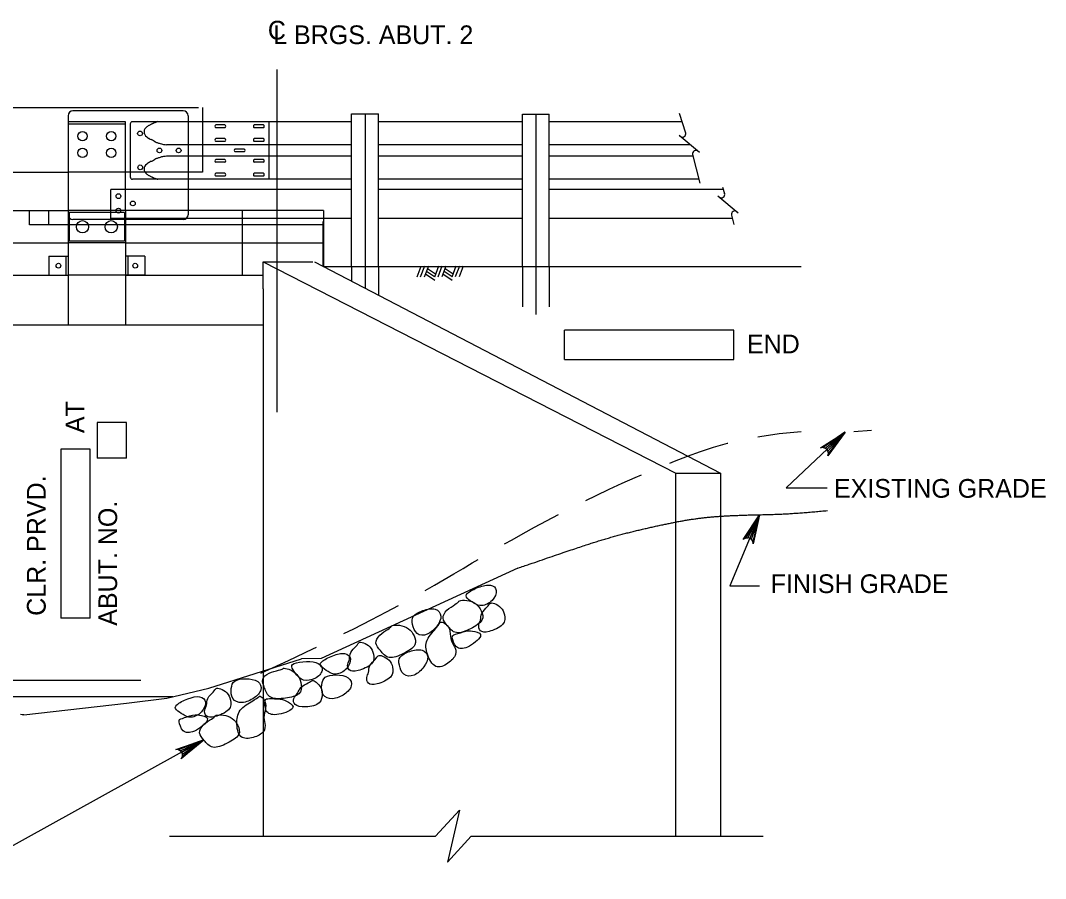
# Model space of a CAD drawing. Extents: x 638268 to 640277, y 295465 to 298435.
# Drawn here: x 638721.7 to 638886.1, y 297402.2 to 297539.8 of the extents above; entities that cross this region are included whole.
import ezdxf

# ---------------------------------------------------------------- set-up
doc = ezdxf.new("R2010")
doc.units = 0
for name, color, linetype in [('2', 7, 'Continuous'), ('3', 7, 'Continuous'), ('4', 7, 'Continuous'), ('8', 7, 'Continuous'), ('Level 25', 7, 'Continuous')]:
    doc.layers.add(name, color=color, linetype=linetype)

msp = doc.modelspace()

# ---------------------------------------------------------------- linework, layer by layer
at = {"layer": '2'}
for p, q in [((638577.23, 297525.9), (638750.23, 297525.9)), ((638750.88, 297525.9), (638750.88, 297523.59)), ((638738.57, 297523.59), (638729.33, 297523.59)), ((638729.33, 297523.59), (638729.33, 297509.34)), ((638738.57, 297523.21), (638729.33, 297523.21)), ((638738.57, 297509.34), (638738.57, 297523.59)), ((638739.3, 297523.23), (638739.3, 297514.73)), ((638750.88, 297523.6), (638739.67, 297523.6)), ((638761.47, 297523.6), (638750.88, 297523.6)), ((638750.88, 297523.59), (638750.88, 297515.51)), ((638754.49, 297523.09), (638753.02, 297523.09)), ((638754.49, 297522.63), (638753.02, 297522.63)), ((638760.67, 297523.09), (638759.19, 297523.09)), ((638760.67, 297522.63), (638759.19, 297522.63)), ((638761.54, 297523.6), (638761.54, 297514.36)), ((638774.81, 297523.6), (638761.54, 297523.6)), ((638802.21, 297523.6), (638779.14, 297523.6)), ((638827.83, 297523.6), (638806.53, 297523.6)), ((638754.49, 297520.88), (638753.02, 297520.88)), ((638754.49, 297520.41), (638753.02, 297520.41)), ((638760.67, 297520.88), (638759.19, 297520.88)), ((638760.67, 297520.41), (638759.19, 297520.41)), ((638750.88, 297519.91), (638745.14, 297519.91)), ((638774.81, 297519.91), (638750.88, 297519.91)), ((638757.59, 297519.21), (638756.11, 297519.21)), ((638757.59, 297518.75), (638756.11, 297518.75)), ((638802.21, 297519.91), (638779.14, 297519.91)), ((638829.15, 297519.91), (638806.53, 297519.91)), ((638750.88, 297518.06), (638745.14, 297518.06)), ((638774.81, 297518.06), (638750.88, 297518.06)), ((638754.49, 297517.55), (638753.02, 297517.55)), ((638754.49, 297517.09), (638753.02, 297517.09)), ((638760.67, 297517.55), (638759.19, 297517.55)), ((638760.67, 297517.09), (638759.19, 297517.09)), ((638802.21, 297518.06), (638779.14, 297518.06)), ((638829.59, 297518.06), (638806.53, 297518.06)), ((638688.94, 297515.51), (638729.33, 297515.51)), ((638738.57, 297515.51), (638729.33, 297515.51)), ((638748.58, 297515.51), (638738.57, 297515.51)), ((638750.88, 297515.51), (638748.58, 297515.51)), ((638748.58, 297514.36), (638739.67, 297514.36)), ((638774.81, 297514.36), (638748.58, 297514.36)), ((638754.49, 297515.33), (638753.02, 297515.33)), ((638754.49, 297514.87), (638753.02, 297514.87)), ((638760.67, 297515.33), (638759.19, 297515.33)), ((638760.67, 297514.87), (638759.19, 297514.87)), ((638802.21, 297514.36), (638779.14, 297514.36)), ((638830.52, 297514.36), (638806.53, 297514.36)), ((638736.22, 297508.08), (638736.22, 297512.7)), ((638748.58, 297512.7), (638736.22, 297512.7)), ((638774.81, 297512.7), (638748.58, 297512.7)), ((638802.21, 297512.7), (638779.14, 297512.7)), ((638834.45, 297512.7), (638806.53, 297512.7)), ((638688.94, 297509.34), (638729.33, 297509.34)), ((638723.16, 297507.04), (638723.16, 297509.34)), ((638726.25, 297507.04), (638726.25, 297509.34)), ((638738.57, 297509.34), (638729.33, 297509.34)), ((638729.33, 297509.34), (638729.33, 297491.02)), ((638738.41, 297509.06), (638729.52, 297509.06)), ((638729.52, 297509.06), (638729.52, 297504.45)), ((638738.41, 297509.06), (638738.41, 297504.45)), ((638770.32, 297509.34), (638738.57, 297509.34)), ((638738.57, 297509.34), (638738.57, 297491.02)), ((638748.58, 297509.34), (638748.58, 297508.68)), ((638770.3, 297508.08), (638736.21, 297508.08)), ((638774.81, 297508.08), (638770.32, 297508.08)), ((638802.21, 297508.08), (638779.14, 297508.08)), ((638835.9, 297508.08), (638806.53, 297508.08)), ((638770.3, 297507.04), (638723.15, 297507.04)), ((638688.94, 297504.15), (638729.33, 297504.15)), ((638738.57, 297504.15), (638729.33, 297504.15)), ((638738.41, 297504.45), (638729.52, 297504.45)), ((638726.24, 297502.05), (638729.33, 297502.05)), ((638726.24, 297502.05), (638726.24, 297498.96)), ((638728.97, 297502.05), (638728.97, 297498.96)), ((638729.33, 297502.05), (638729.33, 297498.96)), ((638741.66, 297502.05), (638738.57, 297502.05)), ((638738.57, 297502.05), (638738.57, 297498.96)), ((638738.93, 297502.05), (638738.93, 297498.96)), ((638741.66, 297502.05), (638741.66, 297498.96)), ((638726.24, 297498.96), (638729.33, 297498.96)), ((638738.57, 297498.96), (638729.33, 297498.96)), ((638741.66, 297498.96), (638738.57, 297498.96))]:
    msp.add_line(p, q, dxfattribs=at)
for centre, radius in [((638731.65, 297521.28), 0.748), ((638736.26, 297521.28), 0.748), ((638740.88, 297521.72), 0.385), ((638731.65, 297518.59), 0.748), ((638736.26, 297518.59), 0.748), ((638743.99, 297518.99), 0.385), ((638747.07, 297518.99), 0.385), ((638740.91, 297516.27), 0.385), ((638737.41, 297511.65), 0.385), ((638739.72, 297510.49), 0.385), ((638737.41, 297509.34), 0.385), ((638731.65, 297506.75), 0.978), ((638736.26, 297506.75), 0.978), ((638727.79, 297500.5), 0.385), ((638740.11, 297500.5), 0.385)]:
    msp.add_circle(centre, radius, dxfattribs=at)
for centre, radius, start, end in [((638739.67, 297523.23), 0.369, 90, 180), ((638742.44, 297521.97), 0.916, 120.3532, 238.6149), ((638744.76, 297519.33), 4.42, 125.3229, 129.0151), ((638742.76, 297522.15), 0.955, 117.3798, 125.3229), ((638756.95, 297494.76), 31.8, 116.5749, 117.3798), ((638743.8, 297521.04), 2.42, 113.6547, 116.5749), ((638745.21, 297517.82), 5.93, 112.3149, 113.6547), ((638767.53, 297463.43), 64.73, 111.9093, 112.3149), ((638744.08, 297521.73), 1.88, 108.4934, 111.9093), ((638746.71, 297513.88), 10.17, 107.0234, 108.4934), ((638753.16, 297522.86), 0.269, 120.8559, 239.1441), ((638754.36, 297522.86), 0.269, 300.8559, 59.1441), ((638759.33, 297522.86), 0.269, 120.8559, 239.1441), ((638760.53, 297522.86), 0.269, 300.8559, 59.1441), ((638745.19, 297524.93), 4.94, 229.2007, 233.1182), ((638742.88, 297521.85), 1.09, 233.1182, 241.475), ((638929.96, 297866.04), 392.83, 241.475, 241.5275), ((638682.44, 297409.64), 126.36, 61.435, 61.5275), ((638687.83, 297419.55), 115.08, 61.2499, 61.435), ((638753.5, 297539.25), 21.45, 241.2499, 241.6785), ((638743.63, 297520.93), 0.644, 241.6785, 249.7671), ((638753.16, 297520.65), 0.269, 120.8559, 239.1441), ((638754.36, 297520.65), 0.269, 300.8559, 59.1441), ((638759.33, 297520.65), 0.269, 120.8559, 239.1441), ((638760.53, 297520.65), 0.269, 300.8559, 59.1441), ((638749.69, 297537.38), 18.18, 249.7671, 251.2889), ((638744.87, 297523.15), 3.14, 251.2889, 252.6389), ((638771.37, 297607.92), 91.96, 252.6389, 252.8885), ((638744.95, 297522.09), 2.16, 252.8885, 261.633), ((638745.37, 297524.93), 5.03, 261.633, 267.3571), ((638756.25, 297518.98), 0.269, 120.8559, 239.1441), ((638757.45, 297518.98), 0.269, 300.8559, 59.1441), ((638742.88, 297516.12), 1.09, 118.525, 126.8818), ((638929.96, 297171.93), 392.83, 118.4725, 118.525), ((638682.44, 297628.32), 126.36, 298.4725, 298.565), ((638687.83, 297618.42), 115.08, 298.565, 298.7501), ((638753.5, 297498.71), 21.45, 118.3215, 118.7501), ((638743.63, 297517.03), 0.644, 110.2329, 118.3215), ((638749.69, 297500.58), 18.18, 108.7111, 110.2329), ((638744.87, 297514.82), 3.14, 107.3611, 108.7111), ((638771.37, 297430.05), 91.96, 107.1115, 107.3611), ((638744.95, 297515.88), 2.16, 98.367, 107.1115), ((638745.37, 297513.03), 5.03, 92.6429, 98.367), ((638753.16, 297517.32), 0.269, 120.8559, 239.1441), ((638754.36, 297517.32), 0.269, 300.8559, 59.1441), ((638759.33, 297517.32), 0.269, 120.8559, 239.1441), ((638760.53, 297517.32), 0.269, 300.8559, 59.1441), ((638742.44, 297516), 0.916, 121.3851, 239.6468), ((638745.19, 297513.04), 4.94, 126.8818, 130.7993), ((638739.67, 297514.73), 0.369, 180, 270), ((638744.76, 297518.64), 4.42, 230.9849, 234.6771), ((638742.76, 297515.81), 0.955, 234.6771, 242.6202), ((638756.95, 297543.2), 31.8, 242.6202, 243.4251), ((638743.8, 297516.92), 2.42, 243.4251, 246.3453), ((638745.21, 297520.14), 5.93, 246.3453, 247.6851), ((638767.53, 297574.53), 64.73, 247.6851, 248.0907), ((638744.08, 297516.23), 1.88, 248.0907, 251.5066), ((638746.71, 297524.09), 10.17, 251.5066, 252.9766), ((638753.16, 297515.1), 0.269, 120.8559, 239.1441), ((638754.36, 297515.1), 0.269, 300.8559, 59.1441), ((638759.33, 297515.1), 0.269, 120.8559, 239.1441), ((638760.53, 297515.1), 0.269, 300.8559, 59.1441)]:
    msp.add_arc(centre, radius, start, end, dxfattribs=at)
at = {"layer": '3'}
for p, q in [((638774.81, 297524.87), (638779.14, 297524.87)), ((638774.81, 297500.4), (638774.81, 297524.87)), ((638776.98, 297524.87), (638776.98, 297496.9)), ((638779.14, 297500.4), (638779.14, 297524.87)), ((638802.21, 297524.79), (638806.53, 297524.79)), ((638802.21, 297500.4), (638802.21, 297524.79)), ((638804.37, 297524.79), (638804.37, 297492.7)), ((638806.53, 297500.4), (638806.53, 297524.79)), ((638827.39, 297524.97), (638828.4, 297521.82)), ((638827.34, 297521.43), (638830.6, 297518.69)), ((638829.52, 297518.35), (638830.67, 297513.75)), ((638834.33, 297513.09), (638834.64, 297512.09)), ((638833.58, 297511.71), (638836.84, 297508.97)), ((638757.31, 297498.96), (638757.31, 297509.34)), ((638770.32, 297509.34), (638770.32, 297500.4)), ((638770.25, 297500.4), (638770.25, 297507.61)), ((638835.76, 297508.63), (638836.14, 297507.12)), ((638738.55, 297504.15), (638770.32, 297504.15)), ((638760.65, 297501.12), (638826.85, 297467.24)), ((638760.65, 297496.79), (638760.65, 297501.12)), ((638760.65, 297501.12), (638768.58, 297501.12)), ((638768.86, 297501.12), (638833.99, 297467.24)), ((638770.25, 297500.4), (638846.91, 297500.4)), ((638774.81, 297500.4), (638774.81, 297498.02)), ((638779.14, 297500.4), (638779.14, 297495.77)), ((638785.94, 297500.4), (638785.27, 297498.64)), ((638785.94, 297500.4), (638785.27, 297498.64)), ((638786.49, 297500.41), (638785.82, 297498.65)), ((638786.49, 297500.41), (638785.82, 297498.65)), ((638787.13, 297500.42), (638786.46, 297498.66)), ((638787.13, 297500.42), (638786.46, 297498.66)), ((638786.66, 297499.19), (638788.16, 297498.16)), ((638786.66, 297499.19), (638788.16, 297498.16)), ((638786.83, 297499.64), (638788.12, 297498.75)), ((638786.83, 297499.64), (638788.12, 297498.75)), ((638786.99, 297500.07), (638788.28, 297499.18)), ((638786.99, 297500.07), (638788.28, 297499.18)), ((638788.75, 297500.42), (638788.1, 297498.68)), ((638788.75, 297500.42), (638788.1, 297498.68)), ((638789.3, 297500.42), (638788.64, 297498.69)), ((638789.3, 297500.42), (638788.64, 297498.69)), ((638789.93, 297500.43), (638789.28, 297498.7)), ((638789.93, 297500.43), (638789.28, 297498.7)), ((638789.47, 297499.21), (638790.97, 297498.17)), ((638789.47, 297499.21), (638790.97, 297498.17)), ((638789.64, 297499.65), (638790.93, 297498.76)), ((638789.64, 297499.65), (638790.93, 297498.76)), ((638789.8, 297500.08), (638791.09, 297499.19)), ((638789.8, 297500.08), (638791.09, 297499.19)), ((638791.56, 297500.43), (638790.91, 297498.69)), ((638791.56, 297500.43), (638790.91, 297498.69)), ((638792.11, 297500.43), (638791.45, 297498.7)), ((638792.11, 297500.43), (638791.45, 297498.7)), ((638792.74, 297500.43), (638792.09, 297498.71)), ((638792.74, 297500.43), (638792.09, 297498.71)), ((638802.21, 297500.4), (638802.21, 297493.91)), ((638806.53, 297500.4), (638806.53, 297493.91)), ((638688.94, 297498.96), (638729.33, 297498.96)), ((638738.57, 297498.96), (638760.65, 297498.96)), ((638760.65, 297496.79), (638760.65, 297435.29)), ((638568.29, 297491.02), (638747.07, 297491.02)), ((638568.29, 297491.02), (638760.65, 297491.02)), ((638854.01, 297473.83), (638844.53, 297464.9)), ((638826.85, 297467.24), (638833.99, 297467.24)), ((638826.85, 297459.39), (638826.85, 297467.24)), ((638833.99, 297467.24), (638833.99, 297460.29)), ((638844.53, 297464.9), (638851.13, 297464.9)), ((638833.99, 297460.29), (638833.99, 297409.02)), ((638840.25, 297460.55), (638835.49, 297449.16)), ((638826.85, 297409.02), (638826.85, 297459.39)), ((638801.5, 297452), (638769.91, 297437.52)), ((638835.49, 297449.16), (638840.25, 297449.16)), ((638769.91, 297437.52), (638766.76, 297437.44)), ((638760.65, 297435.29), (638760.65, 297409.02)), ((638574.64, 297431.41), (638746.15, 297431.41)), ((638788.26, 297409.02), (638792.1, 297413.19)), ((638792.1, 297413.19), (638790.18, 297404.84)), ((638745.58, 297409.02), (638788.26, 297409.02)), ((638790.18, 297404.84), (638794.02, 297409.02)), ((638794.02, 297409.02), (638840.85, 297409.02))]:
    msp.add_line(p, q, dxfattribs=at)
for points in [[(638851.46, 297472.11), (638852.14, 297471.39), (638853.95, 297473.78)], [(638838.65, 297458.02), (638839.56, 297457.64), (638840.25, 297460.55)]]:
    msp.add_lwpolyline(points, close=True, dxfattribs=at)
for centre, radius, start, end in [((638827.9, 297521.65), 0.533, 227.8504, 17.8504), ((638830.04, 297518.47), 0.533, 49.9832, 192.5218), ((638830.04, 297518.47), 0.533, 49.9832, 49.9972), ((638834.14, 297511.93), 0.533, 227.8504, 17.8504), ((638836.28, 297508.75), 0.533, 49.9832, 192.5218), ((638836.28, 297508.74), 0.533, 49.9832, 49.9972), ((638721.7, 297417.02), 11.48, 87.4213, 90)]:
    msp.add_arc(centre, radius, start, end, dxfattribs=at)
for points, degree in [([(638801.5, 297452), (638809.28, 297454.69), (638816.43, 297457.02), (638823.58, 297458.76), (638830.33, 297460.07), (638836.68, 297460.51), (638845.21, 297460.65), (638851.17, 297461.24)], 2), ([(638793.37, 297447.17), (638793.61, 297446.91), (638794.48, 297446.36), (638795.58, 297445.72), (638797.56, 297446.65), (638798.32, 297448.58), (638797.24, 297449.49), (638795.21, 297449.05), (638793.04, 297447.91), (638793.13, 297447.43), (638793.37, 297447.17)], 3), ([(638791.96, 297446.61), (638791.9, 297446.53), (638791.57, 297446.24), (638789.98, 297445.33), (638789.19, 297443.89), (638790.19, 297442.84), (638791.39, 297441.21), (638793.97, 297442.22), (638796.19, 297443.63), (638795.64, 297445.23), (638794.86, 297446.35), (638793.25, 297446.96), (638791.9, 297446.75), (638792.01, 297446.7), (638791.96, 297446.61)], 3), ([(638795.49, 297443.67), (638795.42, 297443.37), (638795.12, 297443), (638795.27, 297441.78), (638796.62, 297441.61), (638799.51, 297442.86), (638799.42, 297444.62), (638798.9, 297445.72), (638797.64, 297446.42), (638796.99, 297446.46), (638796.69, 297445.84), (638795.52, 297444.81), (638795.56, 297443.97), (638795.49, 297443.67)], 3), ([(638784.73, 297444.27), (638784.45, 297443.9), (638784.49, 297443.07), (638785.11, 297441.24), (638786.96, 297441.1), (638788.7, 297442.73), (638789.4, 297444.36), (638788.43, 297445.7), (638786.16, 297445.29), (638785.01, 297444.64), (638784.73, 297444.27)], 3), ([(638789.05, 297443.31), (638788.91, 297443.22), (638788.8, 297442.76), (638786.54, 297440.45), (638786.79, 297438.24), (638788.19, 297435.65), (638790.38, 297436.66), (638791.8, 297438.17), (638791.33, 297439.54), (638790.57, 297440.56), (638790.72, 297442.4), (638789.63, 297443.3), (638789.19, 297443.4), (638789.05, 297443.31)], 3), ([(638781.18, 297442.63), (638781.13, 297442.55), (638780.79, 297442.26), (638779.21, 297441.34), (638778.41, 297439.91), (638779.42, 297438.86), (638780.62, 297437.23), (638783.2, 297438.23), (638785.42, 297439.65), (638784.87, 297441.24), (638784.08, 297442.37), (638782.48, 297442.98), (638781.13, 297442.77), (638781.24, 297442.72), (638781.18, 297442.63)], 3), ([(638791.5, 297441.39), (638791.08, 297441.24), (638790.78, 297441.14), (638791.48, 297439.08), (638793.2, 297438.91), (638796.32, 297441.37), (638794.48, 297441.9), (638793.29, 297442), (638791.92, 297441.53), (638791.5, 297441.39)], 3), ([(638774.47, 297437.38), (638774.4, 297437.08), (638774.1, 297436.71), (638774.25, 297435.49), (638775.59, 297435.32), (638778.49, 297436.57), (638778.39, 297438.32), (638777.88, 297439.42), (638776.62, 297440.13), (638775.97, 297440.16), (638775.67, 297439.55), (638774.49, 297438.52), (638774.53, 297437.68), (638774.47, 297437.38)], 3), ([(638769.98, 297436.19), (638770.22, 297435.93), (638771.09, 297435.38), (638772.19, 297434.73), (638774.18, 297435.67), (638774.93, 297437.6), (638773.85, 297438.51), (638771.83, 297438.07), (638769.65, 297436.92), (638769.74, 297436.45), (638769.98, 297436.19)], 3), ([(638782.63, 297437.72), (638782.35, 297437.35), (638782.39, 297436.52), (638783.01, 297434.69), (638784.85, 297434.55), (638786.6, 297436.18), (638787.3, 297437.81), (638786.33, 297439.15), (638784.06, 297438.74), (638782.91, 297438.09), (638782.63, 297437.72)], 3), ([(638765.28, 297435.94), (638765.43, 297435.61), (638766.07, 297434.81), (638766.9, 297433.84), (638769.08, 297434.08), (638770.43, 297435.66), (638769.69, 297436.87), (638767.64, 297437.11), (638765.21, 297436.74), (638765.14, 297436.26), (638765.28, 297435.94)], 3), ([(638777.53, 297435.26), (638777.47, 297434.96), (638777.16, 297434.59), (638777.31, 297433.37), (638778.66, 297433.2), (638781.55, 297434.45), (638781.46, 297436.21), (638780.95, 297437.31), (638779.69, 297438.01), (638779.03, 297438.04), (638778.73, 297437.43), (638777.56, 297436.4), (638777.6, 297435.56), (638777.53, 297435.26)], 3), ([(638763.77, 297435.87), (638763.68, 297435.8), (638763.28, 297435.64), (638761.48, 297435.29), (638760.26, 297434.19), (638760.87, 297432.88), (638761.48, 297430.94), (638764.24, 297431.06), (638766.8, 297431.67), (638766.8, 297433.36), (638766.42, 297434.68), (638765.1, 297435.77), (638763.76, 297436.02), (638763.85, 297435.93), (638763.77, 297435.87)], 3), ([(638770.6, 297434.49), (638770.21, 297434.23), (638769.98, 297433.43), (638769.98, 297431.49), (638771.68, 297430.77), (638773.85, 297431.73), (638775.05, 297433.06), (638774.56, 297434.63), (638772.28, 297434.99), (638770.98, 297434.75), (638770.6, 297434.49)], 3), ([(638756.08, 297433.88), (638755.7, 297433.62), (638755.46, 297432.82), (638755.46, 297430.89), (638757.16, 297430.16), (638759.34, 297431.13), (638760.53, 297432.45), (638760.05, 297434.03), (638757.77, 297434.38), (638756.47, 297434.14), (638756.08, 297433.88)], 3), ([(638766.15, 297431.94), (638765.99, 297431.67), (638765.59, 297431.43), (638765.33, 297430.22), (638766.55, 297429.62), (638769.69, 297429.87), (638770.17, 297431.56), (638770.05, 297432.76), (638769.08, 297433.84), (638768.48, 297434.08), (638767.99, 297433.6), (638766.55, 297433.01), (638766.31, 297432.2), (638766.15, 297431.94)], 3), ([(638751.53, 297430.01), (638751.46, 297429.71), (638751.16, 297429.34), (638751.31, 297428.12), (638752.66, 297427.95), (638755.55, 297429.2), (638755.46, 297430.95), (638754.94, 297432.06), (638753.68, 297432.76), (638753.03, 297432.79), (638752.73, 297432.18), (638751.56, 297431.15), (638751.6, 297430.31), (638751.53, 297430.01)], 3), ([(638746.73, 297429.28), (638746.97, 297429.02), (638747.84, 297428.47), (638748.94, 297427.83), (638750.93, 297428.76), (638751.68, 297430.69), (638750.6, 297431.59), (638748.58, 297431.16), (638746.4, 297430.02), (638746.49, 297429.54), (638746.73, 297429.28)], 3), ([(638760.03, 297431.44), (638759.87, 297431.4), (638759.62, 297431), (638756.73, 297429.55), (638756.25, 297427.38), (638756.73, 297424.48), (638759.13, 297424.72), (638760.96, 297425.69), (638760.96, 297427.13), (638760.58, 297428.34), (638761.31, 297430.03), (638760.58, 297431.24), (638760.19, 297431.48), (638760.03, 297431.44)], 3), ([(638761.64, 297431.07), (638761.19, 297431.07), (638760.87, 297431.07), (638760.87, 297428.9), (638762.44, 297428.17), (638766.19, 297429.49), (638764.62, 297430.59), (638763.53, 297431.07), (638762.08, 297431.07), (638761.64, 297431.07)], 3), ([(638747.67, 297427.91), (638747.25, 297427.77), (638746.95, 297427.67), (638747.65, 297425.61), (638749.38, 297425.43), (638752.49, 297427.9), (638750.65, 297428.43), (638749.46, 297428.53), (638748.09, 297428.06), (638747.67, 297427.91)], 3), ([(638752.9, 297428.24), (638752.85, 297428.15), (638752.52, 297427.87), (638750.93, 297426.95), (638750.14, 297425.52), (638751.14, 297424.47), (638752.34, 297422.84), (638754.92, 297423.84), (638757.14, 297425.25), (638756.59, 297426.85), (638755.8, 297427.97), (638754.2, 297428.58), (638752.85, 297428.38), (638752.96, 297428.32), (638752.9, 297428.24)], 3)]:
    msp.add_open_spline(points, degree=degree, dxfattribs=at)
at = {"layer": '4'}
for p, q in [((638762.8, 297531.99), (638762.8, 297477.03)), ((638836.14, 297490.17), (638808.99, 297490.17)), ((638808.99, 297485.47), (638808.99, 297490.17)), ((638836.14, 297485.47), (638836.14, 297490.17)), ((638808.99, 297485.47), (638836.14, 297485.47)), ((638734.02, 297475.36), (638734.02, 297469.61)), ((638738.73, 297475.36), (638734.02, 297475.36)), ((638738.73, 297469.61), (638738.73, 297475.36)), ((638728.18, 297471.1), (638728.18, 297443.95)), ((638732.88, 297471.1), (638728.18, 297471.1)), ((638732.88, 297443.95), (638732.88, 297471.1)), ((638738.73, 297469.61), (638734.02, 297469.61)), ((638732.88, 297443.95), (638728.18, 297443.95)), ((638710.19, 297434.04), (638741.01, 297434.04)), ((638751.11, 297424.45), (638710.89, 297402.22))]:
    msp.add_line(p, q, dxfattribs=at)
for points in [[(638854.01, 297473.83), (638851.22, 297470), (638851.31, 297470.43), (638851.23, 297470.78), (638851.05, 297471.05), (638850.8, 297471.24), (638850.45, 297471.34), (638850.02, 297471.27), (638854.01, 297473.83), (638850.45, 297471.34), (638850.8, 297471.24), (638854.01, 297473.83), (638851.05, 297471.05), (638851.23, 297470.78), (638854.01, 297473.83), (638851.31, 297470.43)], [(638840.25, 297460.55), (638839.26, 297455.91), (638839.16, 297456.34), (638838.95, 297456.63), (638838.68, 297456.8), (638838.37, 297456.87), (638838.01, 297456.82), (638837.64, 297456.59), (638840.25, 297460.55), (638838.01, 297456.82), (638838.37, 297456.87), (638840.25, 297460.55), (638838.68, 297456.8), (638838.95, 297456.63), (638840.25, 297460.55), (638839.16, 297456.34)], [(638722.22, 297428.49), (638738.73, 297430.34), (638745.18, 297431.17), (638751.94, 297432.73), (638766.76, 297437.44)], [(638751.11, 297424.45), (638747.49, 297421.39), (638747.67, 297421.78), (638747.68, 297422.15), (638747.57, 297422.45), (638747.37, 297422.69), (638747.06, 297422.87), (638746.62, 297422.91), (638751.11, 297424.45), (638747.06, 297422.87), (638747.37, 297422.69), (638751.11, 297424.45), (638747.57, 297422.45), (638747.68, 297422.15), (638751.11, 297424.45), (638747.67, 297421.78)]]:
    msp.add_lwpolyline(points, dxfattribs=at)
msp.add_lwpolyline([(638748.29, 297423.42), (638748.78, 297422.56), (638751.11, 297424.45)], close=True, dxfattribs=at)
at = {"layer": '8'}
for p, q in [((638839.98, 297473.07), (638840.31, 297473.13)), ((638840.31, 297473.13), (638843.41, 297473.57)), ((638843.41, 297473.57), (638846.93, 297473.92)), ((638855.4, 297473.92), (638858.22, 297474.11)), ((638830.76, 297470.69), (638832.88, 297471.39)), ((638832.88, 297471.39), (638835.12, 297472.04)), ((638835.12, 297472.04), (638835.17, 297472.05)), ((638826.61, 297469.15), (638828.69, 297469.94)), ((638828.69, 297469.94), (638830.76, 297470.69)), ((638825.86, 297468.85), (638826.61, 297469.15)), ((638818.21, 297465.61), (638820.31, 297466.54)), ((638820.31, 297466.54), (638821.31, 297466.97)), ((638814.04, 297463.67), (638816.12, 297464.65)), ((638816.12, 297464.65), (638818.21, 297465.61)), ((638812.38, 297462.85), (638814.04, 297463.67)), ((638804.17, 297458.57), (638806.06, 297459.59)), ((638806.06, 297459.59), (638807.99, 297460.62)), ((638802.34, 297457.56), (638804.17, 297458.57)), ((638799.37, 297455.87), (638800.57, 297456.56)), ((638800.57, 297456.56), (638802.34, 297457.56)), ((638794.18, 297452.84), (638795.12, 297453.39)), ((638791.21, 297451.08), (638792.7, 297451.96)), ((638792.7, 297451.96), (638794.18, 297452.84)), ((638788.09, 297449.25), (638789.68, 297450.18)), ((638789.68, 297450.18), (638791.21, 297451.08)), ((638786.63, 297448.42), (638788.09, 297449.25)), ((638777.94, 297443.69), (638780.39, 297444.97)), ((638780.39, 297444.97), (638782.33, 297446.02)), ((638775.2, 297442.29), (638777.94, 297443.69)), ((638773.59, 297441.49), (638775.2, 297442.29)), ((638764.68, 297437.21), (638768.61, 297439.06)), ((638768.61, 297439.06), (638769.17, 297439.33)), ((638760.25, 297435.18), (638764.68, 297437.21))]:
    msp.add_line(p, q, dxfattribs=at)
at = {"layer": 'Level 25'}
for p, q in [((638747.81, 297525.33), (638730.11, 297525.33)), ((638729.34, 297524.56), (638729.34, 297523.59)), ((638748.58, 297524.56), (638748.58, 297523.59)), ((638748.58, 297523.59), (638748.58, 297514.36)), ((638748.58, 297514.36), (638748.58, 297509.34)), ((638747.81, 297507.91), (638730.11, 297507.91))]:
    msp.add_line(p, q, dxfattribs=at)
for centre, start, end in [((638730.11, 297524.56), 90, 180), ((638747.81, 297524.56), 0, 90), ((638730.11, 297508.68), 180, 270), ((638747.81, 297508.68), 270, 0)]:
    msp.add_arc(centre, 0.77, start, end, dxfattribs=at)

# ---------------------------------------------------------------- texts
at = {"layer": '4'}
for s, p in [('C', (638761.38, 297536.78)), ('L BRGS. ABUT. 2', (638762.24, 297536.04)), ('END', (638838.24, 297486.46)), ('EXISTING GRADE', (638852.2, 297463.29)), ('FINISH GRADE', (638842.04, 297448))]:
    msp.add_text(s, height=3, dxfattribs=at).set_placement(p)
for s, p in [('AT', (638731.94, 297473.65)), ('CLR. PRVD.', (638725.74, 297444.35)), ('ABUT. NO. ', (638737.2, 297442.75))]:
    msp.add_text(s, height=3, rotation=90, dxfattribs=at).set_placement(p)

doc.saveas('drawing.dxf')
